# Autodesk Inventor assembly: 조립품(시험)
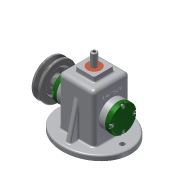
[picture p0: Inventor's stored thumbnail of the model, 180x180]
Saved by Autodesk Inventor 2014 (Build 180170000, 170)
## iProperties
Created: 2017-07
Part Number: 조립품(시험)
Document SubType Name: Assembly
Designer: 702-12
Author: 702-12
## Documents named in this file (16)
- C:\Users\702-12\Desktop\470708V1027\조립품(시험).iam
- C:\Users\702-12\Desktop\470708V1027\본체(시험).ipt
- C:\Users\702-12\Desktop\470708V1027\V벨트풀리.ipt
- C:\Users\702-12\Desktop\470708V1027\고정핀 1.2 x  8.ipt
- C:\Users\702-12\Desktop\470708V1027\뒤커버.ipt
- C:\Users\702-12\Desktop\470708V1027\링크.ipt
- C:\Users\702-12\Desktop\470708V1027\멈춤나사 M3x8.ipt
- C:\Users\702-12\Desktop\470708V1027\베어링 12 x 32 x 10.ipt
- C:\Users\702-12\Desktop\470708V1027\볼트 M4 x 12.ipt
- C:\Users\702-12\Desktop\470708V1027\부시.ipt
- C:\Users\702-12\Desktop\470708V1027\슬라이드.ipt
- C:\Users\702-12\Desktop\470708V1027\앞커버.ipt
- C:\Users\702-12\Desktop\470708V1027\오일실 12 25 7.ipt
- C:\Users\702-12\Desktop\470708V1027\키 4 x 4 x 10.ipt
- C:\Users\702-12\Desktop\470708V1027\편심축.ipt
- C:\Users\702-12\Desktop\470708V1027\핀 5 x 18.ipt
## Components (3 placed, 3 different names)
1. V벨트풀리:1
2. 고정핀 1.2 x  8:1 — 플러쉬:13, 플러쉬:14
3. 핀 5 x 18:1 — 플러쉬:7, 플러쉬:8, 플러쉬:15
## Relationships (5: Flush 5)
- 플러쉬:7 [Flush]: 핀 5 x 18:1
- 플러쉬:8 [Flush]: 핀 5 x 18:1
- 플러쉬:13 [Flush]: 고정핀 1.2 x  8:1
- 플러쉬:14 [Flush]: 고정핀 1.2 x  8:1
- 플러쉬:15 [Flush]: 핀 5 x 18:1
